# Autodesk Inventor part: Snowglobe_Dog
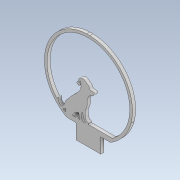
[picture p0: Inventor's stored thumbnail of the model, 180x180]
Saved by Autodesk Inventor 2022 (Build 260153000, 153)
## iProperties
Created: 2021-12
Part Number: Snowglobe_Dog
Material: Generic
Document SubType Name: Modeling
Designer: allis
Density: 1 g/cm^3
Appearance: Default
Author: allis
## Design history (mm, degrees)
sketch "Sketch3"
  geometry: L1 (38.28, -85.585)-(38.282, -85.57); L2 (38.282, -85.57)-(38.284, -85.555); L3 (38.284, -85.555)-(38.286, -85.54); L4 (38.286, -85.54)-(37.895, -85.448); L5 (37.895, -85.448)-(37.503, -85.361); L6 (37.503, -85.361)-(37.113, -85.264); L7 (37.113, -85.264)-(36.459, -85.101); L8 (36.459, -85.101)-(35.785, -85.058); L9 (35.785, -85.058)-(35.123, -84.946); L10 (35.123, -84.946)-(34.94, -84.915); L11 (34.94, -84.915)-(34.742, -84.9); L12 (34.742, -84.9)-(34.574, -85.073); L13 (34.574, -85.073)-(34.84, -85.328); L14 (34.84, -85.328)-(35.103, -85.568); L15 (35.103, -85.568)-(35.45, -85.577); L16 (35.45, -85.577)-(36.393, -85.601); L17 (36.393, -85.601)-(37.336, -85.585); L18 (37.336, -85.585)-(38.28, -85.585); L19 (25.302, -84.633)-(25.729, -84.945); L20 (25.729, -84.945)-(26.11, -85.226); L21 (26.11, -85.226)-(26.495, -85.502); L22 (26.495, -85.502)-(26.575, -85.56); L23 (26.575, -85.56)-(26.671, -85.585); L24 (26.671, -85.585)-(26.774, -85.585); L25 (26.774, -85.585)-(27.165, -85.583); L26 (27.165, -85.583)-(27.556, -85.584); L27 (27.556, -85.584)-(27.961, -85.584); L28 (27.961, -85.584)-(27.904, -84.931); L29 (27.904, -84.931)-(27.893, -84.307); L30 (27.893, -84.307)-(28.074, -83.695); L31 (28.074, -83.695)-(28.126, -83.518); L32 (28.126, -83.518)-(28.085, -83.357); L33 (28.085, -83.357)-(27.938, -83.241); L34 (27.938, -83.241)-(27.773, -83.111); L35 (27.773, -83.111)-(27.597, -83.129); L36 (27.597, -83.129)-(27.43, -83.239); L37 (27.43, -83.239)-(27.301, -83.324); L38 (27.301, -83.324)-(27.186, -83.43); L39 (27.186, -83.43)-(27.052, -83.503); L40 (27.052, -83.503)-(26.462, -83.825); L41 (26.462, -83.825)-(25.926, -84.229); L42 (25.926, -84.229)-(25.302, -84.633); L43 (42.225, -85.564)-(42.049, -85.137); L44 (42.049, -85.137)-(41.92, -84.722); L45 (41.92, -84.722)-(41.797, -84.304); L46 (41.797, -84.304)-(41.587, -83.587); L47 (41.587, -83.587)-(41.471, -82.854); L48 (41.471, -82.854)-(41.398, -82.114); L49 (41.398, -82.114)-(41.343, -81.57); L50 (41.343, -81.57)-(41.293, -81.024); L51 (41.293, -81.024)-(41.3, -80.474); L52 (41.3, -80.474)-(41.305, -80.106); L53 (41.305, -80.106)-(41.154, -80.037); L54 (41.154, -80.037)-(40.812, -80.182); L55 (40.812, -80.182)-(40.385, -80.362); L56 (40.385, -80.362)-(39.953, -80.531); L57 (39.953, -80.531)-(39.524, -80.709); L58 (39.524, -80.709)-(38.677, -81.06); L59 (38.677, -81.06)-(37.842, -81.426); L60 (37.842, -81.426)-(37.161, -82.074); L61 (37.161, -82.074)-(37.012, -82.215); L62 (37.012, -82.215)-(36.989, -82.312); L63 (36.989, -82.312)-(37.089, -82.462); L64 (37.089, -82.462)-(37.144, -82.544)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; 1 further point
  constraints: 10 other
extrude "Extrusion2" new body sketch "Sketch3" distance "d2" = 3.175; taper "d3" = 0 deg
body "Solid2"
